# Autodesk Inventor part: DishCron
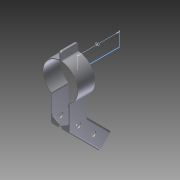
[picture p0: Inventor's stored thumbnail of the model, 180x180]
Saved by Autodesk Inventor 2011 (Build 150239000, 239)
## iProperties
Created: 2014-09
Part Number: DishCron
Document SubType Name: Modeling
Designer: Evgeny
Density: 1 g/cm^3
Author: Evgeny
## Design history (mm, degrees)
sketch "Эскиз1"
  geometry: L1 (11, -18.113)-(11, -28); L2 (-11, -28)-(-11, -18.113); L3 (10, -18.439)-(10, -28); L4 (-10, -28)-(-10, -18.439); L5 (-11, -28)-(-10, -28); L6 (10, -28)-(11, -28); L7 (-1, 22.804)-(-1, 30); L8 (-1, 30)-(1, 30); L9 (1, 30)-(1, 22.804); A1 r 20 centre (0, 0) between (10.909, -16.763) and (-10.909, -16.763); A2 r 2 centre (-12, -18.439) between (-10, -18.439) and (-10.909, -16.763); A3 r 2 centre (12, -18.439) between (10.909, -16.763) and (10, -18.439); A4 r 1 centre (-12, -18.113) between (-11, -18.113) and (-11.03, -17.87); A5 r 1 centre (12, -18.113) between (11.03, -17.87) and (11, -18.113); A6 r 21 centre (0, 0) between (11.03, -17.87) and (2.739, 20.821); A7 r 21 centre (0, 0) between (-2.739, 20.821) and (-11.03, -17.87); A8 r 2 centre (3, 22.804) between (1, 22.804) and (2.739, 20.821); A9 r 2 centre (-3, 22.804) between (-2.739, 20.821) and (-1, 22.804); 7 further points
  constraints: 22 point on circle, 18 end point, 10 tangent, 9 centre point, 6 point on line, 4 equal length, 3 equal radius, 3 perpendicular, 2 coincident, 1 collinear
  dimensions: "d0" = 40 diameter of A1; "d2" = 20 distance between parallel lines of L3 L4; "d3" = 10 distance from line of L3 point (0, 0); "d4" = 22 distance between parallel lines of L1 L2; "d5" = 11 distance from line of L1 point (0, 0); "d8" = 2 radius of A2; "d9" = 1 radius of A4; "d10" = 28 distance from line of L6 point (0, 0); "d11" = 2 distance between parallel lines of L9 L7; "d12" = 1 distance from line of L9 point (0, 0); "d13" = 30 distance from line of L8 point (0, 0); "d14" = 2 radius of A8; "d70" = 21 radius of A6; "d71" = 21 radius of A7
extrude "Выдавливание1" new body sketch "Эскиз1" distance "d15" = 20; taper "d16" = 0 deg
sketch "Эскиз2"
  geometry: L1 (-20, 9.887)-(-20, 0) reference; L2 (0, -13.243)-(28.79, -42.033); L3 (28.79, -42.033)-(15.355, -55.468); L4 (15.355, -55.468)-(-19.128, -20.985); L5 (-19.128, -20.985)-(-20, -20.113); L6 (-20, 9.887)-(-20, -20.113); L7 (-20, 9.887)-(0, 9.887); L8 (0, -13.243)-(0, 9.887); C1 r 3 at (7.931, -34.609); C2 r 3 at (-9.747, -16.931); 1 further point
  constraints: 14 end point, 3 parallel, 2 centre point, 1 collinear, 1 perpendicular, 1 point on line
  dimensions: "d17" = 135 deg angle of L4 L6; "d18" = 19 distance between parallel lines of L4 L2; "d19" = 30 distance of L1.start L5.end; "d20" = 50 distance from line of L3 L5.end; "d48" = 6 diameter of C1; "d49" = 6 diameter of C2; "d50" = 9.5 distance from line of L4 C1.centre; "d51" = 9.5 distance from line of L4 C2.centre; "d52" = 20 distance from line of L3 C1.centre; "d53" = 45 distance from line of C2.centre L3; "d54" = 44.93115 vertical distance of C2.centre point (0, 28) (derived)
extrude "Выдавливание3" join sketch "Эскиз2" distance "d23" = 22; taper "d24" = 0 deg
feature "Оболочка2" dims "d27" = 1
fillet "Сопряжение2" dims "d46" = 2
fillet "Сопряжение3" dims "d47" = 1
extrude "Выдавливание4" cut sketch "Эскиз2" stored distance "d55" = 18; taper "d56" = 0 deg
fillet "Сопряжение4" dims "d57" = 2
sketch "Эскиз3"
  geometry: L1 (-10, -18)-(10, -18); L2 (10, -18)-(10, -38.536); L3 (-10, -38.536)-(-10, -18); L4 (1.5, -46)-(1.5, -88); L5 (1.5, -88)-(-1.5, -88); L6 (-1.5, -88)-(-1.5, -46); L7 (-9.048, -40.24)-(-2.452, -44.296); L8 (2.452, -44.296)-(9.048, -40.24); A1 r 2 centre (-3.5, -46) between (-1.5, -46) and (-2.452, -44.296); A2 r 2 centre (3.5, -46) between (2.452, -44.296) and (1.5, -46); A3 r 2 centre (8, -38.536) between (9.048, -40.24) and (10, -38.536); A4 r 2 centre (-8, -38.536) between (-10, -38.536) and (-9.048, -40.24); A5 r 21 centre (0, 0) between (-2.739, 20.821) and (-11.03, -17.87) reference
  constraints: 16 end point, 8 point on circle, 8 tangent, 4 centre point, 3 equal radius, 2 parallel, 1 horizontal, 1 perpendicular
  dimensions: "d58" = 2 radius of A1; "d61" = 18 distance from line of A5.centre L1; "d62" = 28 distance from line of A2.centre L1; "d63" = 28 distance from line of L1 A1.centre; "d64" = 70 distance from line of L5.end L1; "d65" = 3 distance between parallel lines of L4 L6; "d66" = 1.5 distance from line of L4 A5.centre; "d67" = 10 distance from line of L3 A5.centre; "d68" = 20 distance between parallel lines of L2 L3
extrude "Выдавливание5" cut sketch "Эскиз3" stored distance "d59" = 18; taper "d60" = 0 deg
sketch "Эскиз4"
  geometry: L1 (0, 0)-(0, -50); 1 further point
  constraints: 2 end point, 1 coincident, 1 vertical
  dimensions: "d69" = 50 distance of L1.end point (0, 0)
node "Твердое тело1"
other parameters: "d1" = 42
